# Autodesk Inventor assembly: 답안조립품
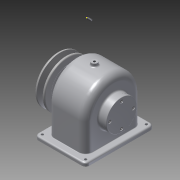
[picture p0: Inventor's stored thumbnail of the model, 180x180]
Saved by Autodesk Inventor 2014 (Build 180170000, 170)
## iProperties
Created: 2016-01
Part Number: 답안조립품
Document SubType Name: Assembly
Designer: SCD-A13
Author: SCD-A13
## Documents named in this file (16)
- C:\Users\SCD-A13\Desktop\460105V1034\답안조립품.iam
- C:\Users\SCD-A13\Desktop\460105V1034\1.본체.ipt
- C:\Users\SCD-A13\Desktop\460105V1034\V-벨트풀리.ipt
- C:\Users\SCD-A13\Desktop\460105V1034\뒤커버.ipt
- C:\Users\SCD-A13\Desktop\460105V1034\멈춤나사 - M4x10.ipt
- C:\Users\SCD-A13\Desktop\460105V1034\베어링 6203.ipt
- C:\Users\SCD-A13\Desktop\460105V1034\볼트 M3 x 8.ipt
- C:\Users\SCD-A13\Desktop\460105V1034\볼트 M3 x 10.ipt
- C:\Users\SCD-A13\Desktop\460105V1034\부시1.ipt
- C:\Users\SCD-A13\Desktop\460105V1034\부시2.ipt
- C:\Users\SCD-A13\Desktop\460105V1034\스퍼기어.ipt
- C:\Users\SCD-A13\Desktop\460105V1034\앞커버.ipt
- C:\Users\SCD-A13\Desktop\460105V1034\오일씰 28 40 8.ipt
- C:\Users\SCD-A13\Desktop\460105V1034\축.ipt
- C:\Users\SCD-A13\Desktop\460105V1034\키 - 5 x 5 x 18.ipt
- C:\Users\SCD-A13\Desktop\460105V1034\키 - 6 x 6 x 22.ipt
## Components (10 placed, 4 different names)
1. 1.본체:1
2. V-벨트풀리:1 — 각도:4
3. ISO 4762 M3 x 8:1
4. ISO 4762 M3 x 8:2
5. ISO 4762 M3 x 8:3
6. ISO 4762 M3 x 8:4
7. ISO 4762 M3 x 10:1
8. ISO 4762 M3 x 10:2
9. ISO 4762 M3 x 10:3
10. ISO 4762 M3 x 10:4
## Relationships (1: Angle 1)
- 각도:4 [Angle]: V-벨트풀리:1
